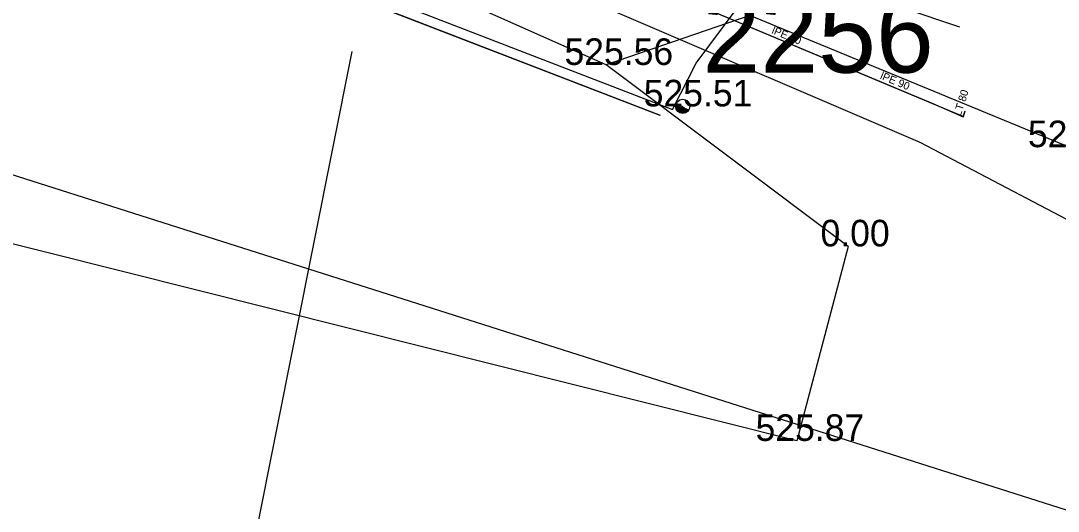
# Model space of a CAD drawing. Extents: x -669393 to -668650, y -1126925 to -1126294.
# Drawn here: x -668932.53 to -668903.24, y -1126829.82 to -1126815.98 of the extents above; entities that cross this region are included whole.
import ezdxf

# ---------------------------------------------------------------- set-up
doc = ezdxf.new("R2010")
doc.units = 0
for name, color, linetype in [('G_Bod_tecka', 7, 'Continuous'), ('G_Bod_vyska', 7, 'Continuous'), ('G_Plochy_zpevnene', 7, 'Continuous'), ('G_Site-Sloupy', 7, 'Continuous'), ('G_Z_ELsilove_nadz_kotovane', 7, 'Continuous'), ('G_Z_ELsilove_podz_kotovane', 7, 'Continuous'), ('G_Z_KANAL_podz_priblizne', 7, 'Continuous'), ('G_Z_PLYNY_podz_geodeticky', 7, 'Continuous'), ('G_Z_SPOJE_podz_geodeticky', 7, 'Continuous'), ('G_Z_SPOJE_podz_kotovane', 7, 'Continuous'), ('G_Z_SPOJE_podz_priblizne', 7, 'Continuous'), ('G_Z_VODA_podz_kotovane', 7, 'Continuous'), ('G_Zelen-okraj', 7, 'Continuous'), ('Vrstva 1', 7, 'Continuous'), ('Vrstva 18', 7, 'Continuous'), ('Vrstva 25', 7, 'Continuous'), ('Vrstva 27', 7, 'Continuous'), ('Vrstva 4', 7, 'Continuous'), ('Vrstva 62', 7, 'Continuous'), ('Vrstva 7', 7, 'Continuous')]:
    doc.layers.add(name, color=color, linetype=linetype)

msp = doc.modelspace()

# ---------------------------------------------------------------- linework, layer by layer
at = {"layer": 'G_Bod_tecka'}
for p, q in [((-668916, -1126817.23), (-668916, -1126817.23)), ((-668913.84, -1126818.4), (-668913.84, -1126818.4)), ((-668909.17, -1126822.35), (-668909.17, -1126822.35)), ((-668910.62, -1126827.84), (-668910.62, -1126827.84))]:
    msp.add_line(p, q, dxfattribs=at)
at = {"layer": 'G_Plochy_zpevnene'}
for points in [[(-668911.95, -1126815.83), (-668916, -1126817.23), (-668925.6, -1126812.96), (-668924.67, -1126810.39)], [(-668902.93, -1126819.55), (-668911.95, -1126815.83)]]:
    msp.add_lwpolyline(points, dxfattribs=at)
at = {"layer": 'G_Site-Sloupy'}
msp.add_circle((-668913.84, -1126818.4), 0.2, dxfattribs=at)
for radius in [0.18, 0.16, 0.14, 0.12, 0.1, 0.08, 0.06, 0.04, 0.02]:
    msp.add_arc((-668913.84, -1126818.4), radius, 152.3541, 332.3541, dxfattribs=at)
at = {"layer": 'G_Z_ELsilove_nadz_kotovane'}
msp.add_lwpolyline([(-668947.21, -1126805.73), (-668947.21, -1126805.73), (-668945.978, -1126806.2), (-668914.13, -1126818.49)], dxfattribs=at)
at = {"layer": 'G_Z_ELsilove_podz_kotovane'}
for points in [[(-668974.29, -1126824.76), (-668947.36, -1126805.96), (-668914.48, -1126818.65)], [(-668914.13, -1126818.49), (-668913.46, -1126817.18), (-668912.3, -1126815.63), (-668910.91, -1126812.36), (-668910.28, -1126810.86), (-668909.83, -1126808.73), (-668908.72, -1126806.99), (-668908.13, -1126806.2)]]:
    msp.add_lwpolyline(points, dxfattribs=at)
at = {"layer": 'G_Z_KANAL_podz_priblizne'}
msp.add_lwpolyline([(-668952.37, -1126814.08), (-668872.81, -1126839.39), (-668858.24, -1126860.51)], dxfattribs=at)
at = {"layer": 'G_Z_PLYNY_podz_geodeticky'}
msp.add_lwpolyline([(-668906.02, -1126816.16), (-668907.56, -1126815.65), (-668909.31, -1126814.95), (-668914.91, -1126812.8), (-668915.37, -1126812.62), (-668932.47, -1126806.72), (-668941.29, -1126803.68), (-668943.53, -1126802.9), (-668969.68, -1126795.84), (-668985.69, -1126793.26), (-668983.7, -1126777.8), (-668983.17, -1126772.12), (-668982.81, -1126768.98), (-668982.56, -1126765.51), (-668982.4, -1126763.78), (-668980.62, -1126745.39), (-668979.97, -1126737.36), (-668979.74, -1126734.84), (-668978.22, -1126718.38)], dxfattribs=at)
at = {"layer": 'G_Z_SPOJE_podz_geodeticky'}
msp.add_lwpolyline([(-668909.58, -1126889.86), (-668909.77, -1126890.44), (-668921.89, -1126888.17), (-668929.29, -1126886.91), (-668934.51, -1126873.68), (-668923.17, -1126816.85)], dxfattribs=at)
at = {"layer": 'G_Z_SPOJE_podz_kotovane'}
msp.add_lwpolyline([(-668874.36, -1126831.78), (-668883.8, -1126828.77), (-668885.48, -1126827.85), (-668888.02, -1126827.3), (-668901.12, -1126822.58), (-668907.14, -1126819.42), (-668924.36, -1126812.03), (-668938.42, -1126806.85)], dxfattribs=at)
at = {"layer": 'G_Z_SPOJE_podz_priblizne'}
msp.add_lwpolyline([(-668909.58, -1126889.86), (-668909.77, -1126890.44), (-668921.89, -1126888.17), (-668929.29, -1126886.91), (-668934.51, -1126873.68), (-668923.17, -1126816.85)], dxfattribs=at)
at = {"layer": 'G_Z_VODA_podz_kotovane'}
msp.add_line((-668905.92, -1126818.69), (-668905.87, -1126818.52), dxfattribs=at)
msp.add_lwpolyline([(-668926.61, -1126810.16), (-668920.09, -1126812.73), (-668918.27, -1126813.5), (-668906.78, -1126818.32), (-668905.92, -1126818.69)], dxfattribs=at)
at = {"layer": 'G_Zelen-okraj'}
msp.add_line((-668909.17, -1126822.35), (-668916, -1126817.23), dxfattribs=at)
msp.add_lwpolyline([(-668909.17, -1126822.35), (-668910.62, -1126827.84), (-668938.17, -1126820.92), (-668953.85, -1126815.95), (-668955.85, -1126811.84), (-668955.39, -1126809.79), (-668955.24, -1126807.73)], dxfattribs=at)
at = {"layer": 'Vrstva 1'}
msp.add_line((-668914.484, -1126818.649), (-668914.484, -1126818.649), dxfattribs=at)
at = {"layer": 'Vrstva 18'}
msp.add_lwpolyline([(-668952.37, -1126814.08), (-668872.812, -1126839.386), (-668858.241, -1126860.513)], dxfattribs=at)
msp.add_lwpolyline([(-668952.37, -1126814.08), (-668872.812, -1126839.386), (-668858.241, -1126860.513)], dxfattribs=at)
at = {"layer": 'Vrstva 25'}
msp.add_line((-668905.918, -1126818.686), (-668905.866, -1126818.521), dxfattribs=at)
at = {"layer": 'Vrstva 27'}
msp.add_lwpolyline([(-668926.612, -1126810.162), (-668920.093, -1126812.734), (-668918.267, -1126813.501), (-668906.785, -1126818.322), (-668905.918, -1126818.686)], dxfattribs=at)
at = {"layer": 'Vrstva 62'}
msp.add_line((-668947.358, -1126805.955), (-668914.484, -1126818.649), dxfattribs=at)
at = {"layer": 'Vrstva 7'}
msp.add_line((-668905.866, -1126818.521), (-668905.866, -1126818.521), dxfattribs=at)

# ---------------------------------------------------------------- texts
at = {"layer": 'G_Bod_vyska'}
for s, p in [('525.56', (-668917.178, -1126817.23)), ('525.51', (-668914.942, -1126818.4)), ('524.94', (-668904.096, -1126819.55)), ('0.00', (-668909.95, -1126822.35)), ('525.87', (-668911.784, -1126827.84))]:
    msp.add_text(s, height=0.75, dxfattribs=at).set_placement(p)
at = {"layer": 'Vrstva 4'}
msp.add_text('2256', height=2.1939, dxfattribs=at).set_placement((-668913.28, -1126817.447))
for s, rotation, p in [('lPE 90', 337.2588, (-668911.346, -1126816.33)), ('lPE 90', 337.2785, (-668908.286, -1126817.614)), ('LT 80', 72.4115, (-668905.993, -1126818.686))]:
    msp.add_text(s, height=0.2194, rotation=rotation, dxfattribs=at).set_placement(p)

doc.saveas('drawing.dxf')
